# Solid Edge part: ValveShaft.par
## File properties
Author: ptcarter
Template: ANSIMM.PAR
Last saved by: ptcarter
Revision: 41
Application: Solid Edge
Accuracy: 0.99
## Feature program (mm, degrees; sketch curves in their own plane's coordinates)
sketch for "unnamed Protrusion 1" plane through (0, 0, 0) normal (0, 0, 1) x-axis (1, 0, 0)
  circle centre (0, 0) radius 7.5
extrude "unnamed Protrusion 1" add finite 100 along +normal
sketch for "unnamed Protrusion 2" plane through (0, 0, 60) normal (0, 0, 1) x-axis (1, 0, 0)
  circle centre (0, 0) radius 10
extrude "unnamed Protrusion 2" add finite 5 along -normal
chamfer "unnamed Chamfer 1"
sketch for "unnamed Cutout 1" plane through (0, 0, 100) normal (0, 0, 1) x-axis (0, 1, 0)
  line (-9.1652, -4) -> (9.1652, -4)
extrude "unnamed Cutout 1" cut finite 23 along -normal
mirror "unnamed Mirror 1" of "unnamed Cutout 1" about plane through (0, 0, 0) normal (1, 0, 0)
extrude "unnamed Cutout 2" cut finite 23
sketch for "unnamed Cutout 3" plane through (0, 0, 0) normal (0, 0, -1) x-axis (1, 0, 0)
  line (-8.6603, -5) -> (8.6603, -5)
extrude "unnamed Cutout 3" cut finite 7 along -normal
mirror "unnamed Mirror 2" of "unnamed Cutout 3" about plane through (0, 0, 0) normal (0, -1, 0)
extrude "unnamed Cutout 4" cut finite 7
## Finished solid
Body 1: solid body, 17 faces, 34 edges, 20 vertices.
  Faces by surface: plane 12, cylinder 3, cone 2
  Edges by curve: line 16, circle 14, intersection 4
Bounding box of the edges (mm): 20.000 x 20.000 x 100.000, from (-10, -10, 0) to (10, 10, 100).
Cylindrical faces by radius (mm): R7.5 x2, R10 x1
Conical faces (half-angle, radius in mm at the cone's reference point): 45 deg R7.5 x2
Planar faces by outward normal: +x 1, +y 1, +z 4, -x 1, -y 1, -z 4
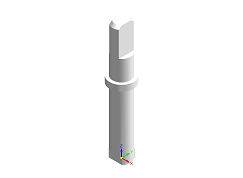
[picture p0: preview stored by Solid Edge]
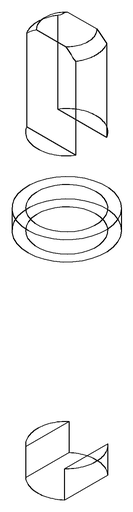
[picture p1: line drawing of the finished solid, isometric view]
